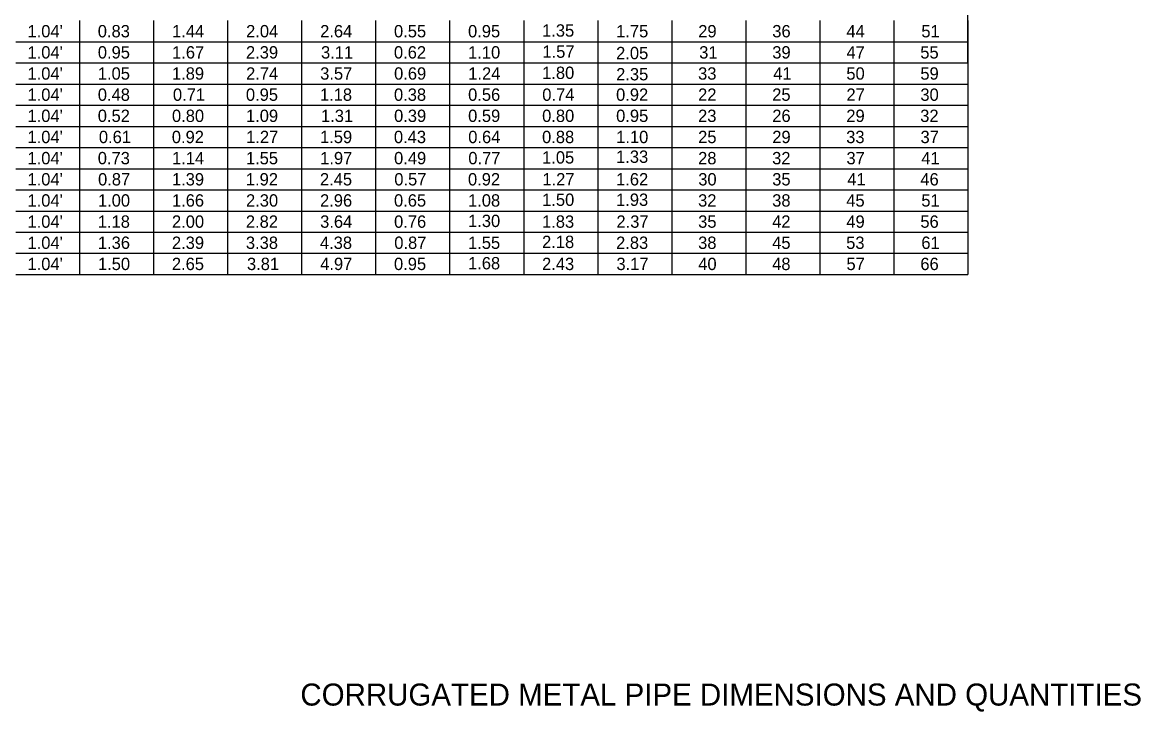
# Model space of a CAD drawing. Extents: x 1.7 to 14.4, y 0 to 7.8.
# Drawn here: x 8.1 to 14.44, y 0.01 to 3.92 of the extents above; entities that cross this region are included whole.
import ezdxf

# ---------------------------------------------------------------- set-up
doc = ezdxf.new("R2010")
doc.units = 0
doc.layers.add('Table', color=7, linetype='Continuous')
doc.layers.add('TextStructures', color=7, linetype='Continuous')

msp = doc.modelspace()

# ---------------------------------------------------------------- linework, layer by layer
at = {"layer": 'Table'}
for points in [[(13.46, 3.93), (13.46, 3.81), (13.46, 3.69), (13.46, 4.53)], [(8.42, 3.93), (8.42, 3.81), (8.42, 3.69), (8.42, 3.57), (8.42, 3.45), (8.42, 3.33), (8.42, 3.21), (8.42, 3.09), (8.42, 2.97), (8.42, 2.85), (8.42, 2.73), (8.42, 2.61), (8.42, 2.49)], [(8.84, 3.93), (8.84, 3.81), (8.84, 3.69), (8.84, 3.57), (8.84, 3.45), (8.84, 3.33), (8.84, 3.21), (8.84, 3.09), (8.84, 2.97), (8.84, 2.85), (8.84, 2.73), (8.84, 2.61), (8.84, 2.49)], [(9.26, 3.93), (9.26, 3.81), (9.26, 3.69), (9.26, 3.57), (9.26, 3.45), (9.26, 3.33), (9.26, 3.21), (9.26, 3.09), (9.26, 2.97), (9.26, 2.85), (9.26, 2.73), (9.26, 2.61), (9.26, 2.49)], [(9.68, 3.93), (9.68, 3.81), (9.68, 3.69), (9.68, 3.57), (9.68, 3.45), (9.68, 3.33), (9.68, 3.21), (9.68, 3.09), (9.68, 2.97), (9.68, 2.85), (9.68, 2.73), (9.68, 2.61), (9.68, 2.49)], [(10.1, 3.93), (10.1, 3.81), (10.1, 3.69), (10.1, 3.57), (10.1, 3.45), (10.1, 3.33), (10.1, 3.21), (10.1, 3.09), (10.1, 2.97), (10.1, 2.85), (10.1, 2.73), (10.1, 2.61), (10.1, 2.49)], [(10.52, 3.93), (10.52, 3.81), (10.52, 3.69), (10.52, 3.57), (10.52, 3.45), (10.52, 3.33), (10.52, 3.21), (10.52, 3.09), (10.52, 2.97), (10.52, 2.85), (10.52, 2.73), (10.52, 2.61), (10.52, 2.49)], [(10.94, 3.93), (10.94, 3.81), (10.94, 3.69), (10.94, 3.57), (10.94, 3.45), (10.94, 3.33), (10.94, 3.21), (10.94, 3.09), (10.94, 2.97), (10.94, 2.85), (10.94, 2.73), (10.94, 2.61), (10.94, 2.49)], [(11.36, 3.93), (11.36, 3.81), (11.36, 3.69), (11.36, 3.57), (11.36, 3.45), (11.36, 3.33), (11.36, 3.21), (11.36, 3.09), (11.36, 2.97), (11.36, 2.85), (11.36, 2.73), (11.36, 2.61), (11.36, 2.49)], [(11.78, 3.93), (11.78, 3.81), (11.78, 3.69), (11.78, 3.57), (11.78, 3.45), (11.78, 3.33), (11.78, 3.21), (11.78, 3.09), (11.78, 2.97), (11.78, 2.85), (11.78, 2.73), (11.78, 2.61), (11.78, 2.49)], [(12.2, 3.93), (12.2, 3.81), (12.2, 3.69), (12.2, 3.57), (12.2, 3.45), (12.2, 3.33), (12.2, 3.21), (12.2, 3.09), (12.2, 2.97), (12.2, 2.85), (12.2, 2.73), (12.2, 2.61), (12.2, 2.49)], [(12.62, 3.93), (12.62, 3.81), (12.62, 3.69), (12.62, 3.57), (12.62, 3.45), (12.62, 3.33), (12.62, 3.21), (12.62, 3.09), (12.62, 2.97), (12.62, 2.85), (12.62, 2.73), (12.62, 2.61), (12.62, 2.49)], [(13.04, 3.93), (13.04, 3.81), (13.04, 3.69), (13.04, 3.57), (13.04, 3.45), (13.04, 3.33), (13.04, 3.21), (13.04, 3.09), (13.04, 2.97), (13.04, 2.85), (13.04, 2.73), (13.04, 2.61), (13.04, 2.49)], [(13.46, 3.93), (13.46, 3.81), (13.46, 3.69), (13.46, 3.57), (13.46, 3.45), (13.46, 3.33), (13.46, 3.21), (13.46, 3.09), (13.46, 2.97), (13.46, 2.85), (13.46, 2.73), (13.46, 2.61), (13.46, 2.49)], [(8.06, 3.81), (8.42, 3.81), (8.84, 3.81), (9.26, 3.81), (9.68, 3.81), (10.1, 3.81), (10.52, 3.81), (10.94, 3.81), (11.36, 3.81), (11.78, 3.81), (12.2, 3.81), (12.62, 3.81), (13.04, 3.81), (13.46, 3.81)], [(8.06, 3.69), (8.42, 3.69), (8.84, 3.69), (9.26, 3.69), (9.68, 3.69), (10.1, 3.69), (10.52, 3.69), (10.94, 3.69), (11.36, 3.69), (11.78, 3.69), (12.2, 3.69), (12.62, 3.69), (13.04, 3.69), (13.46, 3.69)], [(8.06, 3.57), (8.42, 3.57), (8.84, 3.57), (9.26, 3.57), (9.68, 3.57), (10.1, 3.57), (10.52, 3.57), (10.94, 3.57), (11.36, 3.57), (11.78, 3.57), (12.2, 3.57), (12.62, 3.57), (13.04, 3.57), (13.46, 3.57)], [(8.06, 3.45), (8.42, 3.45), (8.84, 3.45), (9.26, 3.45), (9.68, 3.45), (10.1, 3.45), (10.52, 3.45), (10.94, 3.45), (11.36, 3.45), (11.78, 3.45), (12.2, 3.45), (12.62, 3.45), (13.04, 3.45), (13.46, 3.45)], [(8.06, 3.33), (8.42, 3.33), (8.84, 3.33), (9.26, 3.33), (9.68, 3.33), (10.1, 3.33), (10.52, 3.33), (10.94, 3.33), (11.36, 3.33), (11.78, 3.33), (12.2, 3.33), (12.62, 3.33), (13.04, 3.33), (13.46, 3.33)], [(8.06, 3.21), (8.42, 3.21), (8.84, 3.21), (9.26, 3.21), (9.68, 3.21), (10.1, 3.21), (10.52, 3.21), (10.94, 3.21), (11.36, 3.21), (11.78, 3.21), (12.2, 3.21), (12.62, 3.21), (13.04, 3.21), (13.46, 3.21)], [(8.06, 3.09), (8.42, 3.09), (8.84, 3.09), (9.26, 3.09), (9.68, 3.09), (10.1, 3.09), (10.52, 3.09), (10.94, 3.09), (11.36, 3.09), (11.78, 3.09), (12.2, 3.09), (12.62, 3.09), (13.04, 3.09), (13.46, 3.09)], [(8.06, 2.97), (8.42, 2.97), (8.84, 2.97), (9.26, 2.97), (9.68, 2.97), (10.1, 2.97), (10.52, 2.97), (10.94, 2.97), (11.36, 2.97), (11.78, 2.97), (12.2, 2.97), (12.62, 2.97), (13.04, 2.97), (13.46, 2.97)], [(8.06, 2.85), (8.42, 2.85), (8.84, 2.85), (9.26, 2.85), (9.68, 2.85), (10.1, 2.85), (10.52, 2.85), (10.94, 2.85), (11.36, 2.85), (11.78, 2.85), (12.2, 2.85), (12.62, 2.85), (13.04, 2.85), (13.46, 2.85)], [(8.06, 2.73), (8.42, 2.73), (8.84, 2.73), (9.26, 2.73), (9.68, 2.73), (10.1, 2.73), (10.52, 2.73), (10.94, 2.73), (11.36, 2.73), (11.78, 2.73), (12.2, 2.73), (12.62, 2.73), (13.04, 2.73), (13.46, 2.73)], [(8.06, 2.61), (8.42, 2.61), (8.84, 2.61), (9.26, 2.61), (9.68, 2.61), (10.1, 2.61), (10.52, 2.61), (10.94, 2.61), (11.36, 2.61), (11.78, 2.61), (12.2, 2.61), (12.62, 2.61), (13.04, 2.61), (13.46, 2.61)], [(8.06, 2.49), (8.42, 2.49), (8.84, 2.49), (9.26, 2.49), (9.68, 2.49), (10.1, 2.49), (10.52, 2.49), (10.94, 2.49), (11.36, 2.49), (11.78, 2.49), (12.2, 2.49), (12.62, 2.49), (13.04, 2.49), (13.46, 2.49)]]:
    msp.add_lwpolyline(points, dxfattribs=at)

# ---------------------------------------------------------------- texts
for s, p in [("1.04'", (8.1254, 3.835)), ('0.83', (8.524, 3.835)), ('1.44', (8.9454, 3.835)), ('2.04', (9.3654, 3.835)), ('2.64', (9.7854, 3.835)), ('29', (11.93, 3.835)), ('36', (12.35, 3.835)), ('44', (12.7706, 3.835)), ('51', (13.1955, 3.835)), ("1.04'", (8.1254, 3.715)), ('0.95', (8.5243, 3.715)), ('1.67', (8.9456, 3.715)), ('2.39', (9.3647, 3.715)), ('3.11', (9.7903, 3.715)), ('31', (11.9355, 3.715)), ('39', (12.35, 3.715)), ('47', (12.7708, 3.715)), ('55', (13.1895, 3.715)), ("1.04'", (8.1254, 3.595)), ('1.05', (8.5243, 3.595)), ('1.89', (8.9447, 3.595)), ('2.74', (9.3654, 3.595)), ('3.57', (9.7856, 3.595)), ('33', (11.9292, 3.595)), ('41', (12.3555, 3.595)), ('50', (12.7701, 3.595)), ('59', (13.19, 3.595)), ("1.04'", (8.1254, 3.475)), ('0.48', (8.5242, 3.475)), ('0.71', (8.9503, 3.475)), ('0.95', (9.3643, 3.475)), ('1.18', (9.7842, 3.475)), ('22', (11.9292, 3.475)), ('25', (12.3495, 3.475)), ('27', (12.7708, 3.475)), ('30', (13.1901, 3.475)), ("1.04'", (8.1254, 3.355)), ('0.52', (8.524, 3.355)), ('0.80', (8.9449, 3.355)), ('1.09', (9.3647, 3.355)), ('1.31', (9.7903, 3.355)), ('23', (11.9292, 3.355)), ('26', (12.35, 3.355)), ('29', (12.77, 3.355)), ('32', (13.1892, 3.355)), ("1.04'", (8.1254, 3.235)), ('0.61', (8.5303, 3.235)), ('0.92', (8.944, 3.235)), ('1.27', (9.3656, 3.235)), ('1.59', (9.7847, 3.235)), ('25', (11.9295, 3.235)), ('29', (12.35, 3.235)), ('33', (12.7692, 3.235)), ('37', (13.1908, 3.235)), ("1.04'", (8.1254, 3.115)), ('0.73', (8.524, 3.115)), ('1.14', (8.9454, 3.115)), ('1.55', (9.3643, 3.115)), ('1.97', (9.7856, 3.115)), ('28', (11.9294, 3.115)), ('32', (12.3492, 3.115)), ('37', (12.7708, 3.115)), ('41', (13.1955, 3.115)), ("1.04'", (8.1254, 2.995)), ('0.87', (8.5256, 2.995)), ('1.39', (8.9447, 2.995)), ('1.92', (9.364, 2.995)), ('2.45', (9.7843, 2.995)), ('30', (11.9301, 2.995)), ('35', (12.3495, 2.995)), ('41', (12.7755, 2.995)), ('46', (13.19, 2.995)), ("1.04'", (8.1254, 2.875)), ('1.00', (8.5249, 2.875)), ('1.66', (8.9447, 2.875)), ('2.30', (9.3649, 2.875)), ('2.96', (9.7847, 2.875)), ('32', (11.9292, 2.875)), ('38', (12.3494, 2.875)), ('45', (12.7695, 2.875)), ('51', (13.1955, 2.875)), ("1.04'", (8.1254, 2.755)), ('1.18', (8.5242, 2.755)), ('2.00', (8.9449, 2.755)), ('2.82', (9.364, 2.755)), ('3.64', (9.7854, 2.755)), ('35', (11.9295, 2.755)), ('42', (12.3492, 2.755)), ('49', (12.77, 2.755)), ('56', (13.19, 2.755)), ("1.04'", (8.1254, 2.635)), ('1.36', (8.5247, 2.635)), ('2.39', (8.9447, 2.635)), ('3.38', (9.3642, 2.635)), ('4.38', (9.7842, 2.635)), ('38', (11.9294, 2.635)), ('45', (12.3495, 2.635)), ('53', (12.7692, 2.635)), ('61', (13.1955, 2.635)), ("1.04'", (8.1254, 2.515)), ('1.50', (8.5249, 2.515)), ('2.65', (8.9443, 2.515)), ('3.81', (9.3703, 2.515)), ('4.97', (9.7856, 2.515)), ('40', (11.9301, 2.515)), ('48', (12.3494, 2.515)), ('57', (12.7708, 2.515)), ('66', (13.19, 2.515))]:
    msp.add_text(s, height=0.07, rotation=0, dxfattribs=at).set_placement(p)
for s, p in [('0.55', (10.2043, 3.835)), ('0.95', (10.6243, 3.835)), ('1.35', (11.0443, 3.839)), ('1.75', (11.4643, 3.835)), ('0.62', (10.204, 3.715)), ('1.10', (10.6246, 3.715)), ('1.57', (11.046, 3.719)), ('2.05', (11.4643, 3.711)), ('0.69', (10.2047, 3.595)), ('1.24', (10.6254, 3.595)), ('1.80', (11.0446, 3.599)), ('2.35', (11.4643, 3.591)), ('0.38', (10.2042, 3.475)), ('0.56', (10.6247, 3.475)), ('0.74', (11.0454, 3.475)), ('0.92', (11.464, 3.475)), ('0.39', (10.2047, 3.355)), ('0.59', (10.6247, 3.355)), ('0.80', (11.0446, 3.355)), ('0.95', (11.4643, 3.355)), ('0.43', (10.2039, 3.235)), ('0.64', (10.6254, 3.235)), ('0.88', (11.0442, 3.235)), ('1.10', (11.4646, 3.235)), ('0.49', (10.2047, 3.115)), ('0.77', (10.6259, 3.115)), ('1.05', (11.0443, 3.119)), ('1.33', (11.464, 3.1231)), ('0.57', (10.2059, 2.995)), ('0.92', (10.624, 2.995)), ('1.27', (11.0459, 2.995)), ('1.62', (11.464, 2.995)), ('0.65', (10.2043, 2.875)), ('1.08', (10.6242, 2.875)), ('1.50', (11.0446, 2.879)), ('1.93', (11.464, 2.879)), ('0.76', (10.2047, 2.755)), ('1.30', (10.6245, 2.759)), ('1.83', (11.044, 2.755)), ('2.37', (11.466, 2.755)), ('0.87', (10.2059, 2.635)), ('1.55', (10.6243, 2.635)), ('2.18', (11.0442, 2.6399)), ('2.83', (11.4641, 2.635)), ('0.95', (10.2043, 2.515)), ('1.68', (10.6242, 2.519)), ('2.43', (11.044, 2.515)), ('3.17', (11.466, 2.515))]:
    msp.add_text(s, height=0.07, dxfattribs=at).set_placement(p)
at = {"layer": 'TextStructures'}
msp.add_text('CORRUGATED METAL PIPE DIMENSIONS AND QUANTITIES', height=0.125, dxfattribs=at).set_placement((9.6733, 0.0447))

doc.saveas('drawing.dxf')
